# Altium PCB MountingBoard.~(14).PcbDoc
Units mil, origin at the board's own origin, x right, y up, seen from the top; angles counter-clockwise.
Board outline 3780 x 10250 mil, 4 copper layers (Top Layer, Internal Plane 1, Internal Plane 2, Bottom Layer); 26 components, 8 nets, 106 pads, 59 vias.
Unrouted connection lines stored in the file: 4.
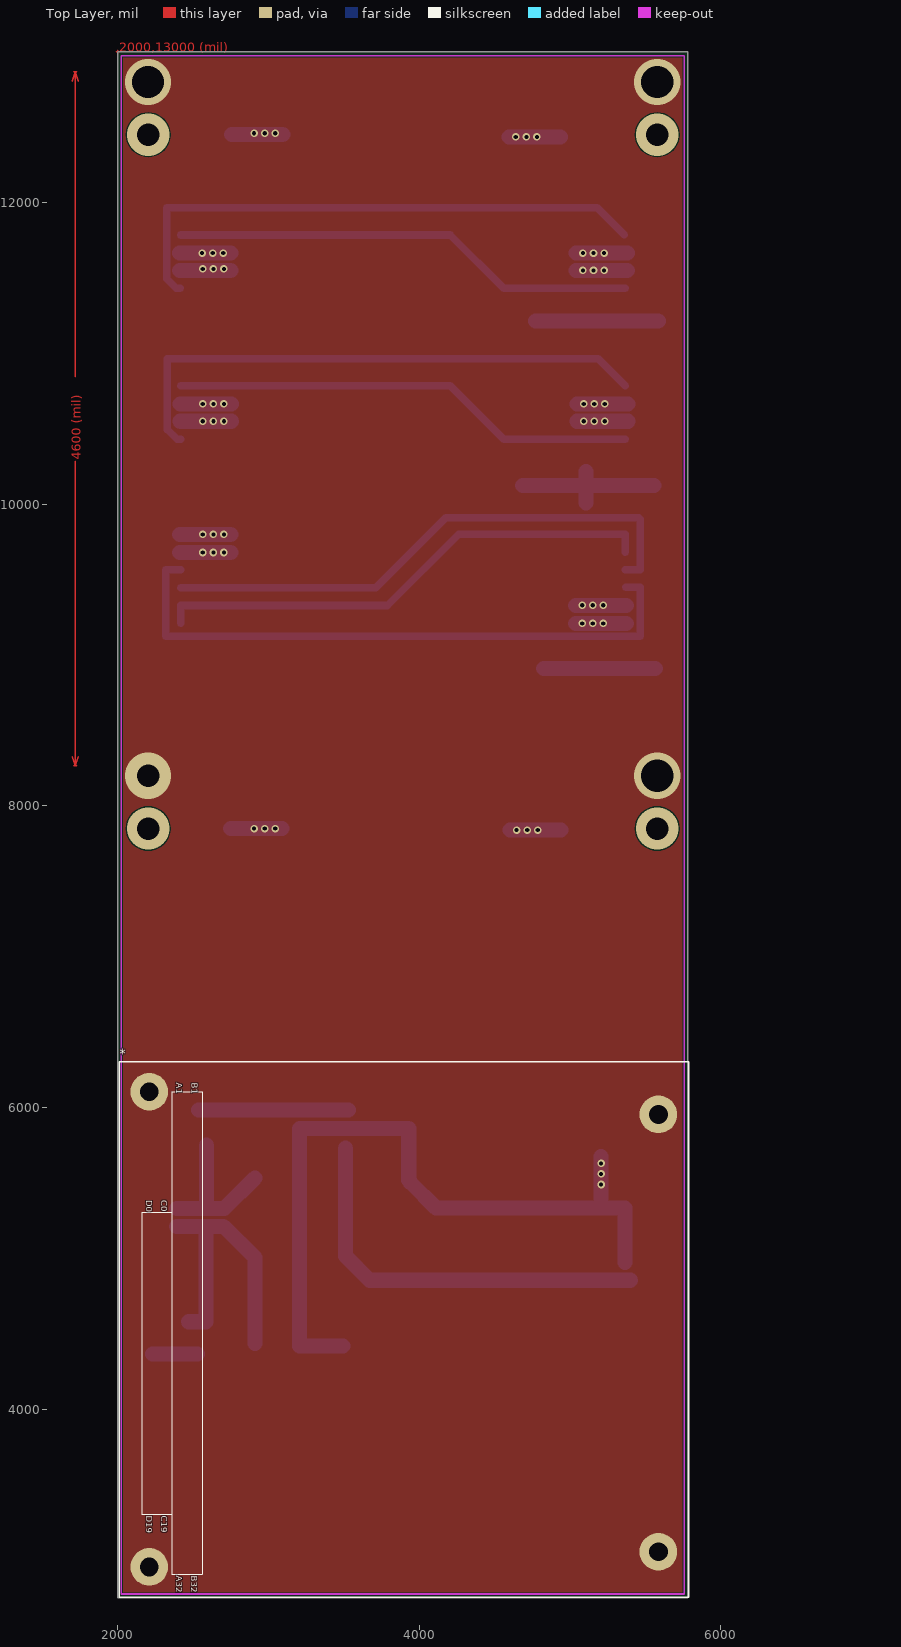
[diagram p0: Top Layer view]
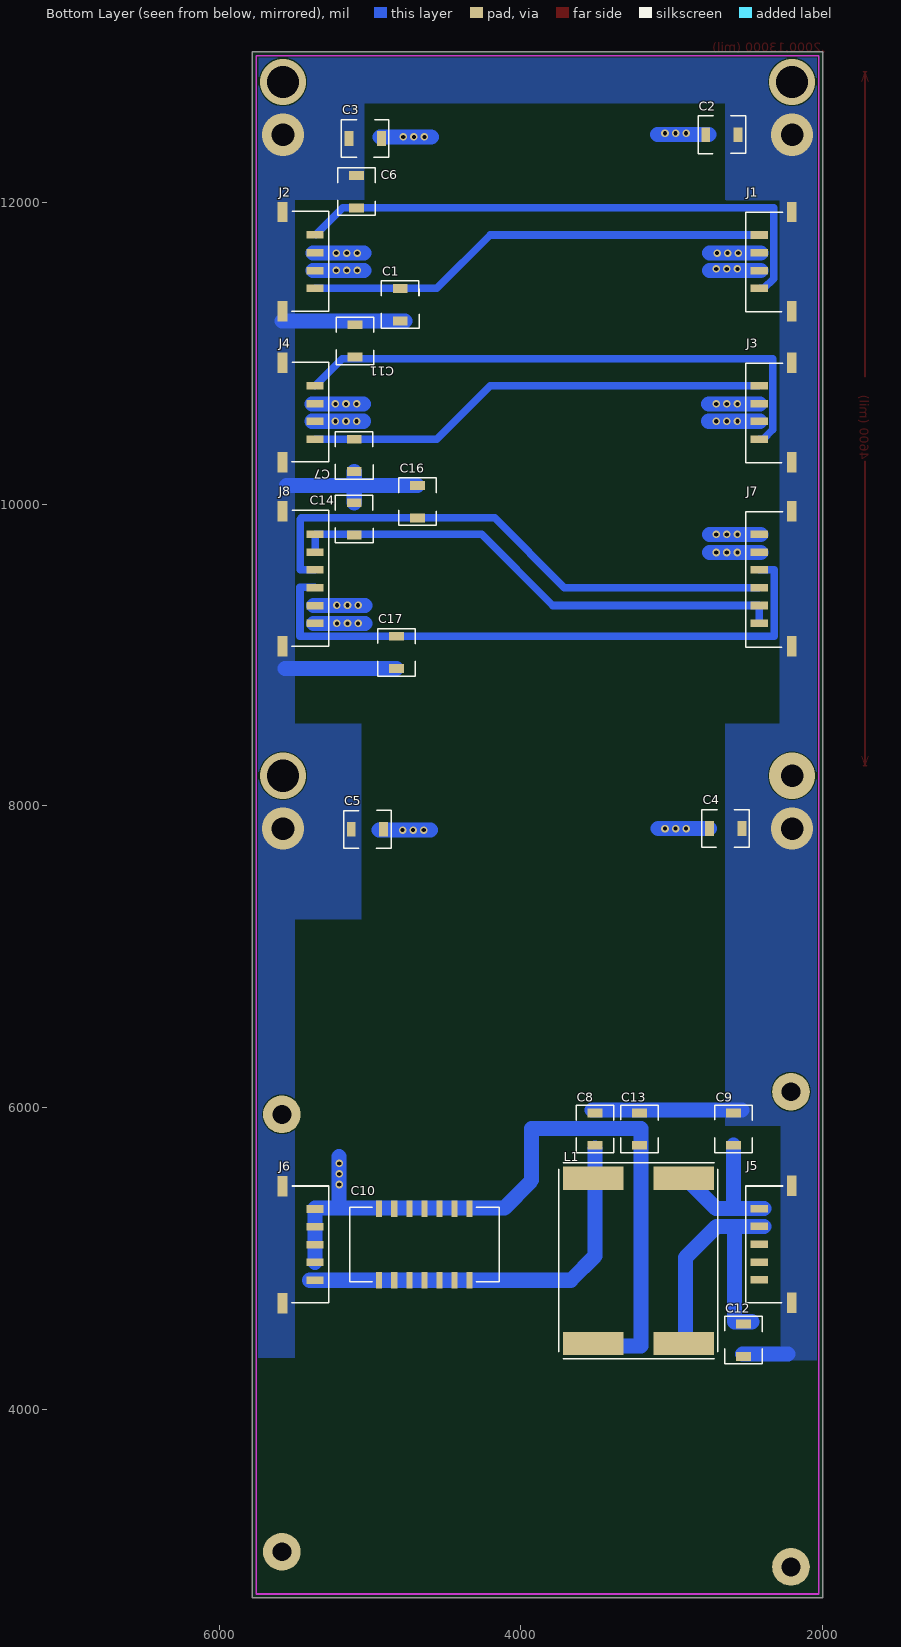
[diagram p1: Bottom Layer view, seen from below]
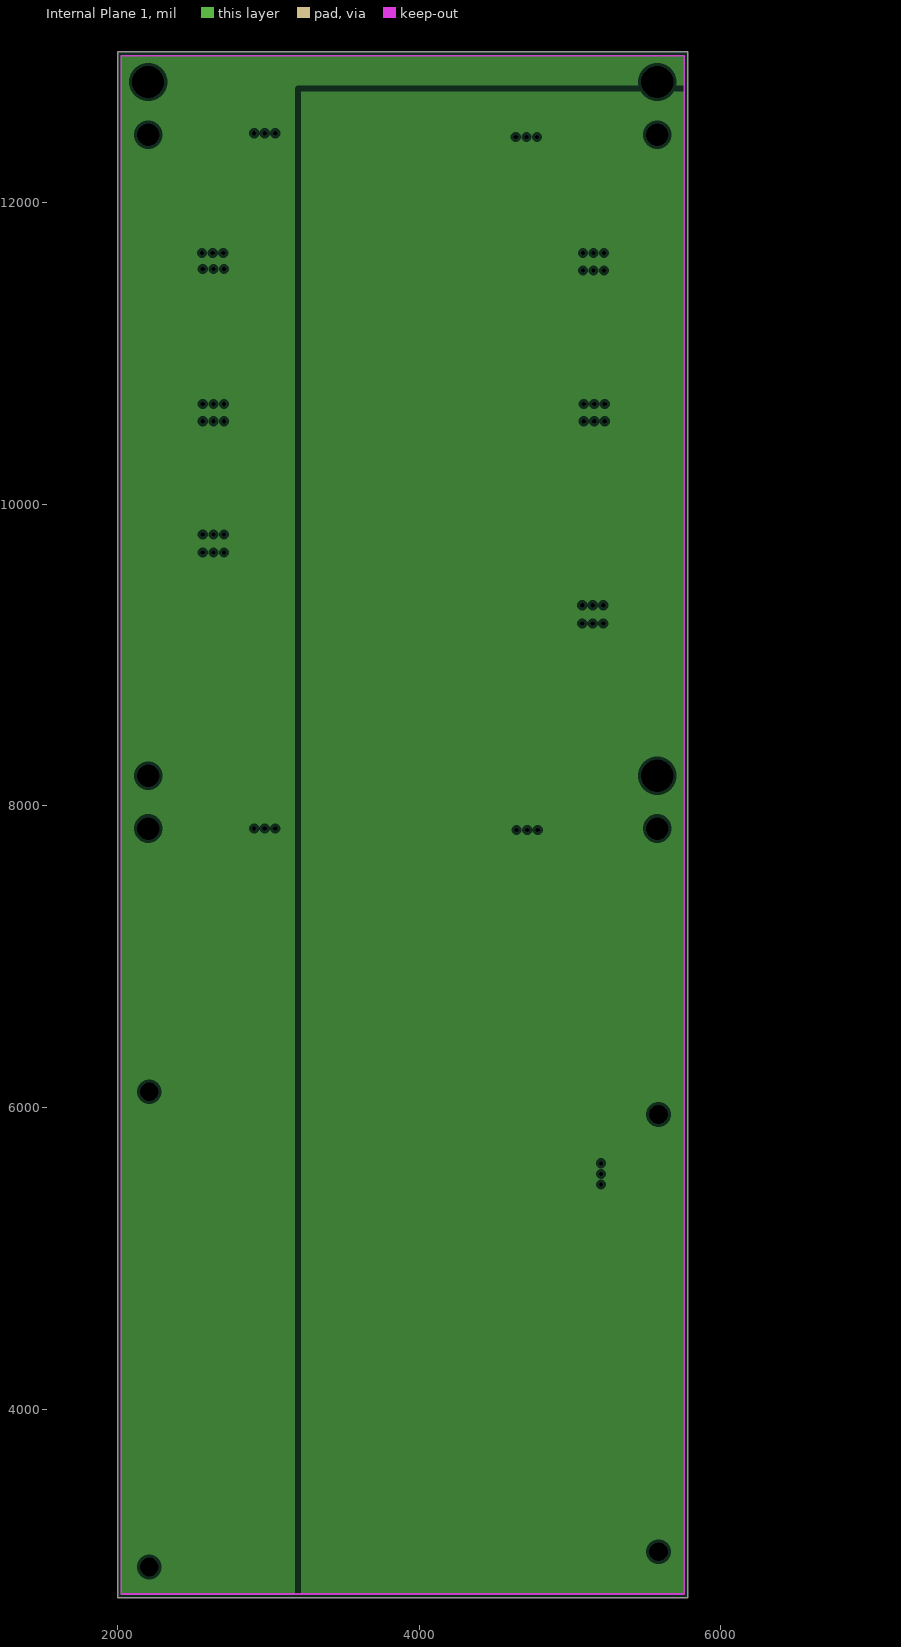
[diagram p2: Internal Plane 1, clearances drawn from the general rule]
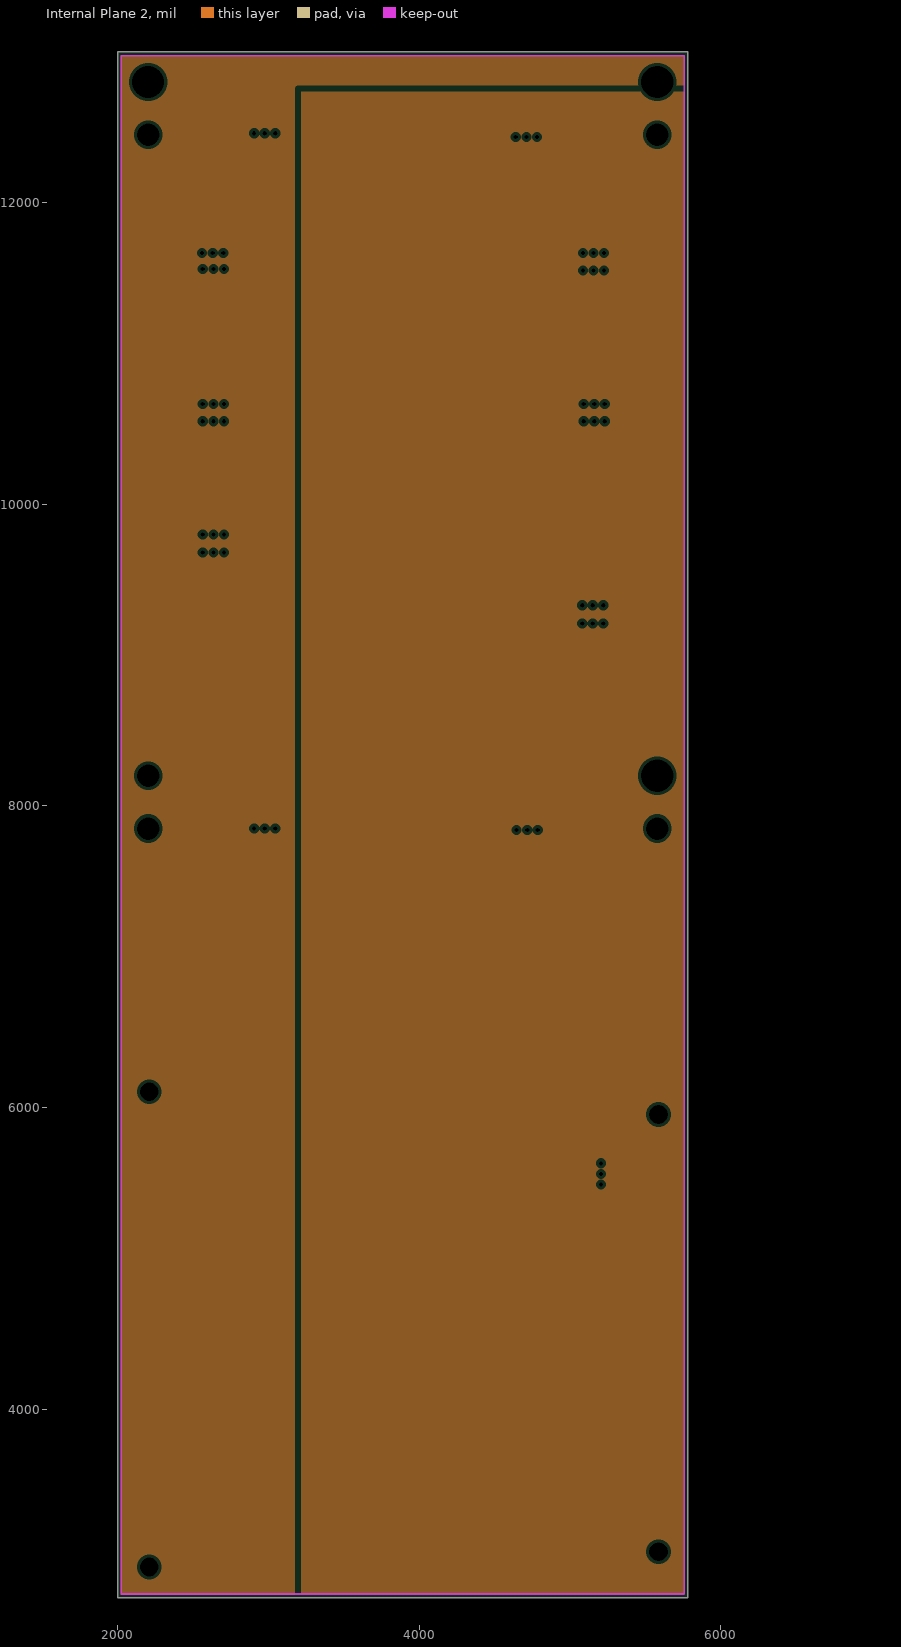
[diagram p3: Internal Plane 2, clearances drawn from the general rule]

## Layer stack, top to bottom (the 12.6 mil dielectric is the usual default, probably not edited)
Top Layer: signal copper 1.4
Dielectric: dielectric 12.6, FR-4, Dk 4.8
Internal Plane 1: plane copper 1.4
Dielectric: dielectric 12.6, FR-4, Dk 4.8
Internal Plane 2: plane copper 1.4
Dielectric: dielectric 12.6, FR-4, Dk 4.8
Bottom Layer: signal copper 1.4

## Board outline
2000,2750 5780,2750 5780,13000 2000,13000

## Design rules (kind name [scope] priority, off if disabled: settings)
Clearance [All] p1: gap=8
PlaneClearance [All] p1: clearance=20
PlaneConnect [All] p1: planeconnectstyle=Direct reliefexpansion=20 reliefentries=4 reliefconductorwidth=10 reliefairgap=10
PolygonConnect [All] p1: connectstyle=Direct reliefconductorwidth=10 reliefentries=4 polygonreliefangle="90 Angle"
RoomDefinition MountingBoard [InComponentClass('MountingBoard')] p1: confinementstyle=ConfineIn formatcopy=TRUE lockcomponents=FALSE outline 5820,3060 1965,3060 1965,13045 5820,13045
RoutingVias [All] p1: holewidth=28 width=50 viastyle="Through Hole" minholewidth=28 minwidth=50 maxholewidth=28 maxwidth=50
SilkscreenOverComponentPads [All] p1: minsilkscreentomaskgap=10
SolderMaskExpansion [All] p1: expansion=4
Width [All] p1: maxlimit=100 minlimit=10 preferedwidth=10 toplayer_maxwidth=10 minimp=50.000000 maximp=50.000000 favimp=50.000000
25 further rules are at their usual default settings.

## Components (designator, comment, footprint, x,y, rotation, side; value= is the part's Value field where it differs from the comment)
* "PC104 Footprint" "PC104 FOOTPRINT" 2215,6105 r270 top
C1 "Cap Semi" 7163 4800,11431 r270 bottom
C2 "Cap Semi" 7163 2560,12450 r0 bottom
C3 "Cap Semi" 7163 5140,12425 r180 bottom
C4 "Cap Semi" 7163 2535,7850 r0 bottom
C5 "Cap Semi" 7163 5125,7845 r180 bottom
C6 "Cap Semi" 7163 5090,12180 r270 bottom
C7 "Cap Semi" 7163 5105,10431 r270 bottom
C8 "Cap Semi" 7163 3510,5965 r270 bottom
C9 "Cap Semi" 7163 2590,5750 r90 bottom
C10 "10uf" CAPSTICK-CS4-7-SMD 4340,4855 r0 bottom
C11 "Cap Semi" 7163 5100,11190 r270 bottom
C12 "Cap Semi" 7163 2525,4350 r90 bottom
C13 "Cap Semi" 7163 3215,5750 r90 bottom
C14 "Cap Semi" 7163 5105,10010 r270 bottom
C16 "Cap Semi" 7163 4685,10125 r270 bottom
C17 "Cap Semi" 7163 4825,8910 r90 bottom
J1 "CON4_SMD" "MICROFIT3-1X4 SMT RA NAIL" 2420,11785 r90 bottom
J2 "CON4_SMD" "MICROFIT3-1X4 SMT RA NAIL" 5365,11431 r270 bottom
J3 "CON4_SMD" "MICROFIT3-1X4 SMT RA NAIL" 2420,10785 r90 bottom
J4 "CON4_SMD" "MICROFIT3-1X4 SMT RA NAIL" 5365,10431 r270 bottom
J5 "CON5_SMD" "MICROFIT3-1X5 SMT RA NAIL" 2420,5330 r90 bottom
J6 "CON5_SMD" "MICROFIT3-1X5 SMT RA NAIL" 5365,4855 r270 bottom
J7 "CON6_SMD" "MICROFIT3-1X6 SMT RA NAIL" 2420,9801 r90 bottom
J8 "CON6_SMD" "MICROFIT3-1X6 SMT RA NAIL" 5365,9210 r270 bottom
L1 "" PULSE_BIGFOOT 2720,5610 r270 bottom

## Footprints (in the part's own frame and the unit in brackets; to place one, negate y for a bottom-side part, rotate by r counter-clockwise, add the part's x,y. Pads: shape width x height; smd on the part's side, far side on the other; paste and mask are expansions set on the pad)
7163 [mm] "7.1 x 6.3 SMD"
  rect 1.5x2.5 smd: 1(0,0) 2(5.461,0)
  silkscreen extent -1.27,-3.18 6.73,3.17
CAPSTICK-CS4-7-SMD [mil] "Capstick CS4 case with 7 leads per side"
  rect 40x110 smd: 1(0,0) 1(100,0) 1(200,0) 1(300,0) 1(400,0) 1(500,0) 1(600,0) 2(0,-475) 2(100,-475) 2(200,-475) 2(300,-475) 2(400,-475) 2(500,-475) 2(600,-475)
  silkscreen extent -195,-485 795,10
"MICROFIT3-1X4 SMT RA NAIL" [mil] "Microfit 3 Single Row 4 Position SMT Right Angle Nail"
  rect 50x115 smd: 1(0,0) 2(-118.11,0) 3(-236.22,0) 4(-354.33,0)
  rect 135x65 smd: nail(-506.5,-215.5) nail(152.5,-215.5)
  silkscreen extent -510,-155 150,90
"MICROFIT3-1X5 SMT RA NAIL" [mil] "Microfit 3.0 Single Row SMT with Nails 5 Position"
  rect 50x115 smd: 1(0,0) 2(-118.11,0) 3(-236.22,0) 4(-354.33,0) 5(-472.44,0)
  rect 135x65 smd: nail(-624.5,-215.5) nail(152.5,-215.5)
  silkscreen extent -625,-155 150,90
"MICROFIT3-1X6 SMT RA NAIL" [mil] "Microfit 3 Single Row 6 Position SMT Right Angle Nail"
  rect 50x115 smd: 1(0,0) 2(-118.11,0) 3(-236.22,0) 4(-354.33,0) 5(-472.44,0) 6(-590.55,0)
  rect 135x65 smd: nail(-743.5,-215.5) nail(152.5,-215.5)
  silkscreen extent -750,-155 150,90
"PC104 FOOTPRINT" [mil] "PC104 Footprint"
  round 250 hole 125: Mnt1(0,-5) Mnt2(3150,-5) Mnt3(3050,3370) Mnt4(150,3370)
  silkscreen extent -200,-205 3350,3570
PULSE_BIGFOOT [mil] "Pulse engineering big foot footprint"
  rect 155x400 smd: 1(77.5,-200) 2(77.5,-800) 3(1174.5,-200) 4(1174.5,-800)
  silkscreen extent -25,-1030 1275,25

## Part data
C1 C2 C3 C4 C5 C6 C7 C8 C9 C11 C12 C13 C14 C16 C17: "Capacitor (Semiconductor SIM Model)"
C10: library part CAPACITOR, "Capacitor"
L1: library part "COMMON MODE CHOKE"

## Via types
v1: diameter 50, hole 28, Top Layer to Bottom Layer, 51 vias
v2: diameter 280, hole 149.5, Top Layer to Bottom Layer, 4 vias
v3: diameter 306, hole 213, Top Layer to Bottom Layer, 3 vias
v4: diameter 306, hole 149.5, Top Layer to Bottom Layer, 1 vias

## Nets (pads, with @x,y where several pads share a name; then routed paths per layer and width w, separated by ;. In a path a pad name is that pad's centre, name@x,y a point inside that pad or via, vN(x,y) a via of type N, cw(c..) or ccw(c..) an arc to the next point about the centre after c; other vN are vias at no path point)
48V+: C9.1 J5.1 L1.1 | length 1008.9
  Bottom Layer w100: J5.1@2390,5330 2702.5,5330 ; 2590,5340 C9.1 ; 2707.5,5330 L1.1@2910,5532.5
48V-: C12.2 J5.2 L1.3 | length 1917.1
  Bottom Layer w100: J5.2@2390,5211.89 2703.11,5211.89 2910,5005 L1.3@2910,4435.5 ; 2470,4580 2585,4580 2585,5206.89
+5V: C1.1 C7.1 C14.2 J1.1 J2.1 J3.1 J4.1 J7.5 J7.6 J8.5 J8.6 | length 9560
  Bottom Layer w50: J7.6 J7.5 3788.56,9328.56 4260.55,9800.55 J8.6 J8.5 ; J3.1 4205,10785 4559,10431 J4.1 ; J1.1 4205,11785 4559,11431 J2.1
+12V: C6.2 C11.2 C16.2 J1.4 J2.4 J3.4 J4.4 J7.4 J8.4 | length 11055.6
  Bottom Layer w50: J1.4@2415,11430.67 2389.33,11430.67 2324.5,11495.5 2324.5,11824.17 2325,11824.67 2325,11965 5180.33,11965 J2.4@5360,11785.33 ; J7.4 3711.67,9446.67 4175,9910 5455,9910 ; J3.4 2394.33,10430.67 2329.5,10495.5 2329.5,10824.17 2330,10824.67 2330,10965 5185.33,10965 J4.4 ; J8.4 5464.33,9564.33 5464.33,9900.67
-12V: C17.2 J7.3 J8.3 | length 4104.7
  Bottom Layer w50: J7.3 2320.22,9564.78 2320.22,9125.22 5464.78,9125.22 5464.78,9449.78 J8.3@5368.56,9449.78
CHASSIS: C1.2 C2.1 C3.1 C4.1 C5.1 C6.1 C7.2 C8.1 C9.2 C11.1 C12.1 C13.2 C14.1 C16.1 C17.1 J1.nail J2.nail J3.nail J4.nail J5.nail J6.nail J7.nail J8.nail | length 4004.2
  Bottom Layer w10: 2490,4390 2530,4365 2550,4390
  Bottom Layer w100: 2230,4365 C12.1@2530,4365 ; 2535,5985 C8.1@3530,5985 ; C16.1 5105,10125 ; C1.2@4770,11215 J2.nail@5584,11215 ; C17.1 5565,8910 ; C14.1 5105,10125 ; C7.2 5105,10125 ; 5555,10125 5105,10125
  other v2: 2202.5,7850 5577.5,7850 2202.5,12450 5577.5,12450
"EDGETECH GROUND": *.Mnt1 *.Mnt2 *.Mnt3 *.Mnt4 C2.2 C3.2 C4.2 C5.2 C10.2 C13.1 J1.2 J1.3 J2.2 J2.3 J3.2 J3.3 J4.2 J4.3 J6.2 J6.3 J6.4 J6.5 J7.1 J7.2 J8.1 J8.2 L1.4 | length 10431.8
  Bottom Layer w100: J7.2@2410,9680 2750,9680 ; J7.1@2410,9800 2750,9800 ; J1.3@2410,11550 2750,11550 ; J1.2@2410,11665 2750,11665 ; J3.3@2415,10550 2755,10550 ; J3.2@2415,10665 2755,10665 ; C4.2 3090,7850 ; C2.2@2755,12450 3095,12450 ; L1.4@3494.5,4420 3205,4420 3205,5860 3930,5860 3930,5520 ; 3940,5505 4110,5335 5365,5335 J6.2 ; 4595,12435 C3.2@4935,12435 ; 4600,7840 4940,7840 ; 5035,9210 J8.1@5375,9210 ; 5035,9330 J8.2@5375,9330 ; 5040,11550 J2.2@5380,11550 ; 5040,11665 J2.3@5380,11665 ; 5045,10550 J4.2@5385,10550 ; 5045,10665 J4.3@5385,10665 ; 5205,5335 5205,5675
  other v1: 5205,5490 5205,5560 5205,5630 4645,7840 4715,7840 4785,7840 2905,7850 2975,7850 3045,7850 5080,9210 5150,9210 5220,9210 5080,9330 5150,9330 5220,9330 2565,9680 2635,9680 2705,9680 2565,9800 2635,9800 2705,9800 2565,10550 2635,10550 2705,10550 5090,10550 5160,10550 5230,10550 2565,10665 2635,10665 2705,10665 5090,10665 5160,10665 5230,10665 5085,11550 5155,11550 5225,11550 2565,11560 2635,11560 2705,11560 2560,11665 2630,11665 2700,11665 5085,11665 5155,11665 5225,11665 4640,12435 4710,12435 4780,12435 2905,12460 2975,12460 3045,12460
  other v3: 5577.5,8200 2202.5,12800 5577.5,12800
  other v4: 2202.5,8200
"FILTER 48V+": C8.2 C10.1 J6.1 L1.2 | length 2671.3
  Bottom Layer w100: C8.2@3510,5730 3510,5015 3670,4855 J6.1@5400,4855
pads on no net: J5.3 J5.4 J5.5
copper on no net: | length 4371.2
  Top Layer w10: 1699.01,8325.91 1719.01,8265.91 ; 1699.01,12805.91 1719.01,12865.91 ; 1709.01,8265.91 1729.01,8265.91 ; 1709.01,12865.91 1729.01,12865.91 ; 1719.01,10285 1719.01,8265.91 ; 1719.01,10846.83 1719.01,12865.91 ; 1739.01,8325.91 1719.01,8265.91 ; 1739.01,12805.91 1719.01,12865.91 ; 1990,13000 2010,13000 ; 2000,12990 2000,13010

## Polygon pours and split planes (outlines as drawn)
CHASSIS on Bottom Layer "Top Layer-No Net" (solid, remove dead copper): 2277.96,5705 2277.96,4326.52 2275,4325 2025,4325 2025,5705
CHASSIS on Bottom Layer "Top Layer-No Net" (solid): 2605,12971.55 2605,12658.45 5073.89,12658.45 5080,12664.36 5080,12979.7
CHASSIS on Bottom Layer "Top Layer-No Net" (solid): 5500,12020 5040,12020 5040,12965 5050,12975 5740,12975 5740,12015
CHASSIS on Bottom Layer "Top Layer-No Net" (solid, remove dead copper): 5500,8545 5060,8545 5060,7250 5500,7250
CHASSIS on Bottom Layer "Top Layer-No Net" (solid, remove dead copper): 5745,4340 5500,4340 5500,12975 5755,12975
CHASSIS on Bottom Layer "Top Layer-No Net" (solid): 2285,8545 2038.25,8545 2038.25,12973.25 2040,12975 2645,12975 2645,12020 2640,12015 2285,12015
CHASSIS on Bottom Layer "Top Layer-No Net" (solid, remove dead copper): 2645,7577.27 2645,5880 2260,5880 2264.5,5901.2 2264.5,7577.27
CHASSIS on Bottom Layer "Chassis" (solid, remove dead copper): 2015,5705 2277.96,5705 2277.96,7489.99 2272.48,7495.32 2645,7495.32 2645,8545 2020.48,8545
"EDGETECH GROUND" on Top Layer "Top Layer-No Net" (solid): 2025,12975 5755,12975 5755,2775 2025,2775
no net on Internal Plane 1 (split plane): 5759.9,2775.1 3215.1,2775.1 3215.1,12734.9 5759.9,12734.9
no net on Internal Plane 1 (split plane): 5759.9,12775.1 3195,12775.1 3191.08,12774.71 3187.31,12773.57 3183.83,12771.71 3180.79,12769.21 3178.29,12766.17 3176.43,12762.69 3175.29,12758.92 3174.9,12755 3174.9,2770.1 2020.1,2770.1 2020.1,12979.9 5759.9,12979.9
no net on Internal Plane 2 (split plane): 5759.9,2775.1 3215.1,2775.1 3215.1,12734.9 5759.9,12734.9
no net on Internal Plane 2 (split plane): 5759.9,12775.1 3195,12775.1 3191.08,12774.71 3187.31,12773.57 3183.83,12771.71 3180.79,12769.21 3178.29,12766.17 3176.43,12762.69 3175.29,12758.92 3174.9,12755 3174.9,2770.1 2020.1,2770.1 2020.1,12979.9 5759.9,12979.9

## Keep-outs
Keep-Out Layer:
  lines w10: 2025,2775 2025,12975 5755,12975 5755,2775 4572.5,2775 2707.5,2775 2025,2775

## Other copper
Top Layer:
  text "2000,13000 (mil)" at 2010,13000 h60
  text "4600 (mil)" at 1755,10295 h60 r90

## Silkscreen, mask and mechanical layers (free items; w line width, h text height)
Drill Drawing:
  text ".LEGEND" at 5980,3200 h60
  text "Drill Drawing." at 5980,3100 h60

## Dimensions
2025,2775 to 5755,2775 on Mechanical 1
1660,2850 to 2030,12990 on Mechanical 1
